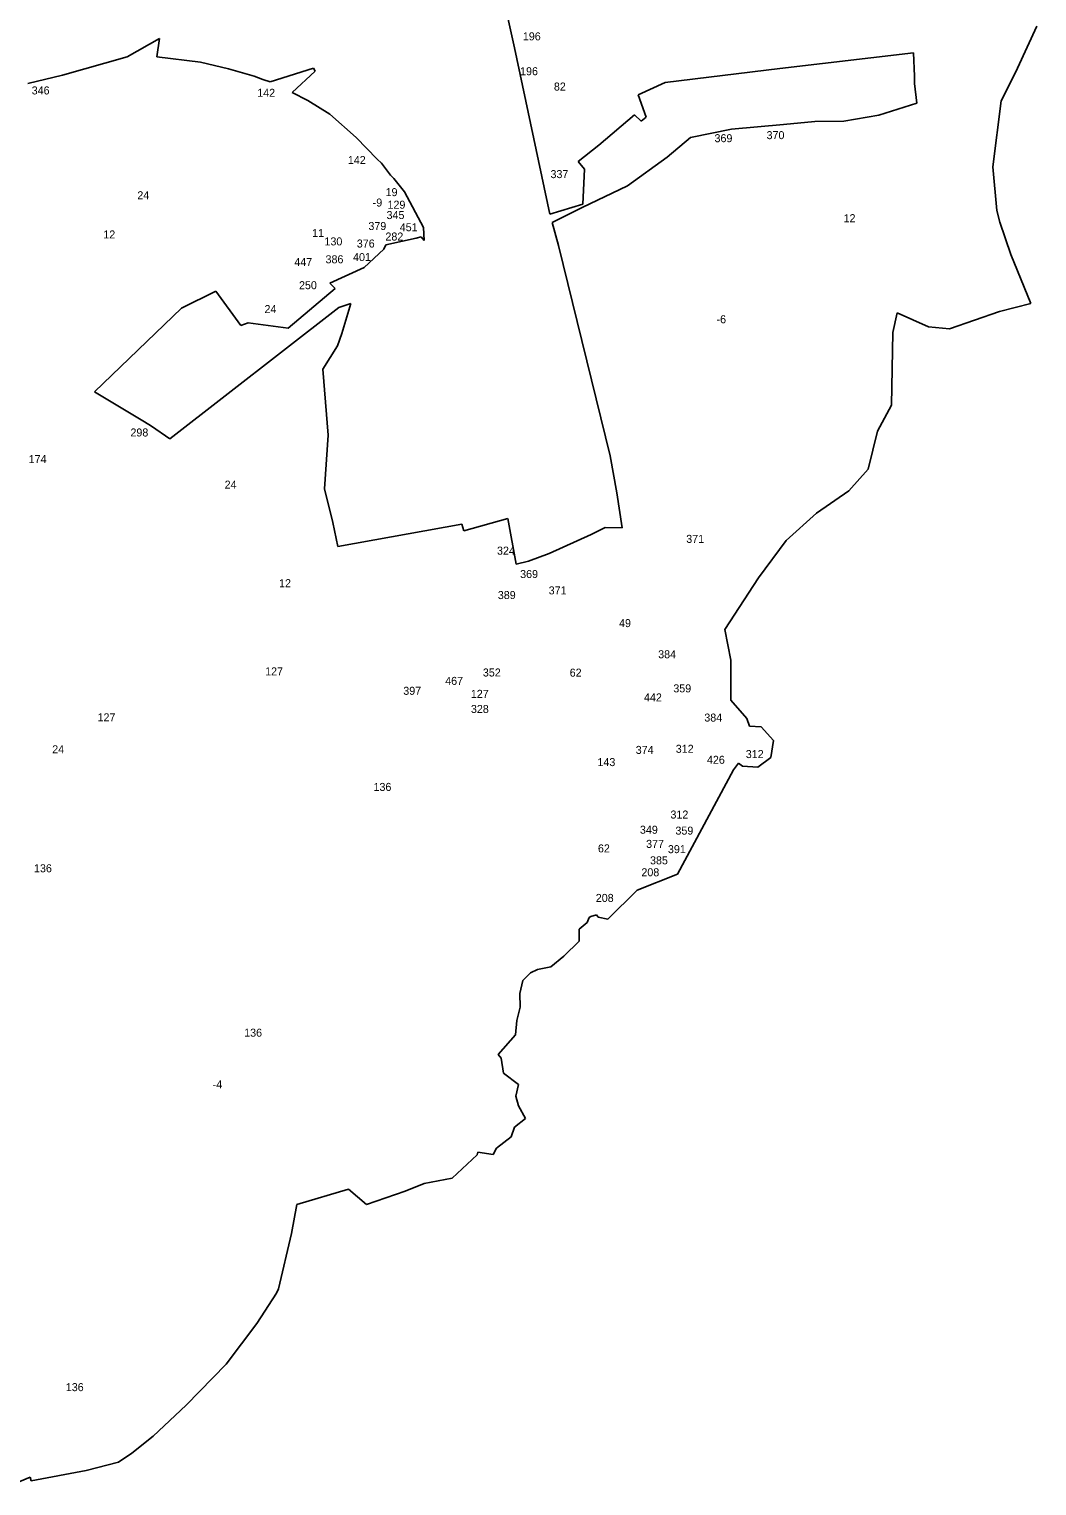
# Model space of a CAD drawing. Extents: x -782019 to -780521, y -973594 to -971888.
# Drawn here: x -781317 to -780625, y -973578 to -972577 of the extents above; entities that cross this region are included whole.
import ezdxf

# ---------------------------------------------------------------- set-up
doc = ezdxf.new("R2010")
doc.units = 0
doc.layers.add('Vrstva 13', color=7, linetype='Continuous')
doc.layers.add('Vrstva 24', color=7, linetype='Continuous')

msp = doc.modelspace()

# ---------------------------------------------------------------- linework, layer by layer
at = {"layer": 'Vrstva 13'}
for p, q in [((-780994.91, -972538.88), (-780983.51, -972589.87)), ((-780638.04, -972603.74), (-780624.8, -972574.84)), ((-781249.52, -972595.92), (-781227.36, -972583.33)), ((-781227.36, -972583.33), (-781229.28, -972595.92)), ((-781294.1, -972608.5), (-781249.52, -972595.92)), ((-781229.28, -972595.92), (-781199.28, -972599.66)), ((-780983.51, -972589.87), (-780959.31, -972704.23)), ((-780801.25, -972604.1), (-780709.62, -972593.28)), ((-780709.62, -972593.28), (-780708.89, -972609.24)), ((-781317.9, -972614.44), (-781294.1, -972608.5)), ((-781199.28, -972599.66), (-781180.09, -972604.18)), ((-781162.4, -972609.19), (-781180.09, -972604.18)), ((-781121.6, -972603.9), (-781151.33, -972613.25)), ((-781120.51, -972605.91), (-781136.37, -972620.64)), ((-781120.51, -972605.91), (-781121.6, -972603.9)), ((-780801.25, -972604.1), (-780880.2, -972613.72)), ((-780649.37, -972626.34), (-780639.72, -972607.18)), ((-780639.72, -972607.18), (-780638.04, -972603.74)), ((-781156.38, -972611.52), (-781162.4, -972609.19)), ((-781151.33, -972613.25), (-781156.38, -972611.52)), ((-780880.2, -972613.72), (-780898.53, -972622.12)), ((-780708.89, -972609.24), (-780708.8, -972614.44)), ((-780708.8, -972614.44), (-780707.34, -972627.76)), ((-781136.37, -972620.64), (-781125.57, -972626.03)), ((-781110.35, -972635.47), (-781125.57, -972626.03)), ((-780898.53, -972622.12), (-780893.15, -972637.57)), ((-780707.34, -972627.76), (-780733.24, -972636.15)), ((-780655.03, -972671.69), (-780649.37, -972626.34)), ((-781110.35, -972635.47), (-781092.33, -972651.47)), ((-780925.66, -972656.64), (-780901.18, -972635.94)), ((-780896.66, -972640.31), (-780901.18, -972635.94)), ((-780896.66, -972640.31), (-780893.15, -972637.57)), ((-780733.24, -972636.15), (-780757.26, -972640.21)), ((-780862.62, -972651.44), (-780834.62, -972645.64)), ((-780798.79, -972642.63), (-780834.62, -972645.64)), ((-780798.79, -972642.63), (-780777.19, -972640.35)), ((-780757.26, -972640.21), (-780777.19, -972640.35)), ((-781077.93, -972666.34), (-781092.33, -972651.47)), ((-780939.84, -972667.86), (-780925.66, -972656.64)), ((-780878.62, -972664.98), (-780862.62, -972651.44)), ((-781075.01, -972669.16), (-781077.93, -972666.34)), ((-781068.63, -972677.28), (-781075.01, -972669.16)), ((-780935.42, -972673.29), (-780939.84, -972667.86)), ((-780906.01, -972684.59), (-780878.62, -972664.98)), ((-781068.63, -972677.28), (-781066.53, -972679.65)), ((-780935.42, -972673.29), (-780936.55, -972697.36)), ((-780652.32, -972701.57), (-780655.03, -972671.69)), ((-781066.53, -972679.65), (-781059.15, -972688.77)), ((-781046.137, -972713.311), (-781059.15, -972688.77)), ((-780937.09, -972699.56), (-780906.01, -972684.59)), ((-780936.55, -972697.36), (-780959.31, -972704.23)), ((-780937.09, -972699.56), (-780957.7, -972709.84)), ((-780650.17, -972709.76), (-780652.32, -972701.57)), ((-781045.7, -972722.37), (-781046.137, -972713.311)), ((-780957.7, -972709.84), (-780953.32, -972725.8)), ((-780642.66, -972731.8), (-780650.17, -972709.76)), ((-781086.91, -972740.92), (-781073.33, -972728.19)), ((-781073.33, -972728.19), (-781071.92, -972725.28)), ((-781071.92, -972725.28), (-781051.13, -972720.72)), ((-781047.75, -972719.73), (-781051.13, -972720.72)), ((-781045.7, -972722.37), (-781047.75, -972719.73)), ((-780953.32, -972725.8), (-780917.77, -972870.37)), ((-780628.85, -972765.64), (-780642.66, -972731.8)), ((-781086.91, -972740.92), (-781110.3, -972751.54)), ((-781212.35, -972768.86), (-781188.65, -972757.19)), ((-781188.65, -972757.19), (-781171.47, -972780.77)), ((-781106.74, -972755.28), (-781139.1, -972782.54)), ((-781110.3, -972751.54), (-781106.74, -972755.28)), ((-781272.02, -972826.28), (-781212.35, -972768.86)), ((-781220.28, -972858.52), (-781104.27, -972768.41)), ((-781095.97, -972765.67), (-781104.27, -972768.41)), ((-781102.26, -972786.1), (-781095.97, -972765.67)), ((-780650.48, -972771.15), (-780628.85, -972765.64)), ((-781166.59, -972778.85), (-781171.47, -972780.77)), ((-781139.1, -972782.54), (-781166.59, -972778.85)), ((-780723.65, -972785.44), (-780720.78, -972771.87)), ((-780720.78, -972771.87), (-780699.31, -972781.61)), ((-780684.87, -972783.05), (-780650.48, -972771.15)), ((-781105.16, -972794.77), (-781102.26, -972786.1)), ((-780724.61, -972835.44), (-780723.65, -972785.44)), ((-780699.31, -972781.61), (-780684.87, -972783.05)), ((-781115.3, -972810.73), (-781105.16, -972794.77)), ((-781111.59, -972856.06), (-781115.3, -972810.73)), ((-781272.02, -972826.28), (-781237.71, -972847.01)), ((-780734.35, -972853.38), (-780724.61, -972835.44)), ((-781237.71, -972847.01), (-781232.87, -972849.81)), ((-781232.87, -972849.81), (-781220.28, -972858.52)), ((-781114.14, -972893), (-781111.59, -972856.06)), ((-780740.74, -972879.41), (-780734.35, -972853.38)), ((-780917.77, -972870.37), (-780913.21, -972895.63)), ((-780753.91, -972894.34), (-780740.74, -972879.41)), ((-781114.14, -972893), (-781108.39, -972916.16)), ((-780913.21, -972895.63), (-780909.61, -972919.71)), ((-780776.09, -972909.75), (-780753.91, -972894.34)), ((-781108.39, -972916.16), (-781104.84, -972932.67)), ((-781104.84, -972932.67), (-781019.78, -972917.26)), ((-781018.41, -972921.91), (-781019.78, -972917.26)), ((-780988.24, -972913.32), (-781018.41, -972921.91)), ((-780988.24, -972913.32), (-780982.5, -972944.74)), ((-780796.92, -972928.55), (-780776.09, -972909.75)), ((-780959.66, -972937.49), (-780930.94, -972924.27)), ((-780930.94, -972924.27), (-780921.19, -972919.57)), ((-780921.19, -972919.57), (-780909.61, -972919.71)), ((-780816, -972954.14), (-780796.92, -972928.55)), ((-780974.02, -972942.69), (-780959.66, -972937.49)), ((-780982.5, -972944.74), (-780974.02, -972942.69)), ((-780839.14, -972989.74), (-780816, -972954.14)), ((-780834.91, -973010.81), (-780839.14, -972989.74)), ((-780835.03, -973038.3), (-780834.91, -973010.81)), ((-780824.01, -973050.8), (-780835.03, -973038.3)), ((-780822.13, -973056.18), (-780824.01, -973050.8)), ((-780814.11, -973056.5), (-780822.13, -973056.18)), ((-780805.73, -973065.97), (-780814.11, -973056.5)), ((-780807.44, -973077.55), (-780805.73, -973065.97)), ((-780816.46, -973084.3), (-780807.44, -973077.55)), ((-780871.72, -973157.85), (-780833.1, -973086.16)), ((-780833.1, -973086.16), (-780829.78, -973081.59)), ((-780829.78, -973081.59), (-780827.07, -973083.46)), ((-780827.07, -973083.46), (-780816.46, -973084.3)), ((-780899.41, -973168.91), (-780871.72, -973157.85)), ((-780919.44, -973188.71), (-780899.41, -973168.91)), ((-780933.6, -973191.12), (-780932.21, -973187.7)), ((-780932.21, -973187.7), (-780931.17, -973186.82)), ((-780931.17, -973186.82), (-780927.26, -973185.78)), ((-780927.26, -973185.78), (-780926.07, -973187.43)), ((-780926.07, -973187.43), (-780919.44, -973188.71)), ((-780939.26, -973195.69), (-780933.6, -973191.12)), ((-780939.14, -973203.86), (-780939.26, -973195.69)), ((-780949.76, -973214.2), (-780939.14, -973203.86)), ((-780958.69, -973221.59), (-780949.76, -973214.2)), ((-780977.89, -973230.85), (-780972.5, -973225.58)), ((-780972.5, -973225.58), (-780967.75, -973223.39)), ((-780967.75, -973223.39), (-780958.69, -973221.59)), ((-780979.88, -973239.87), (-780977.89, -973230.85)), ((-780979.6, -973249.33), (-780979.88, -973239.87)), ((-780982, -973258.42), (-780979.6, -973249.33)), ((-780982.95, -973268.24), (-780982, -973258.42)), ((-780994.76, -973281.67), (-780982.95, -973268.24)), ((-780992.62, -973284.34), (-780994.76, -973281.67)), ((-780991.06, -973294.67), (-780992.62, -973284.34)), ((-780980.85, -973302.43), (-780991.06, -973294.67)), ((-780982.61, -973310.29), (-780980.85, -973302.43)), ((-780980.73, -973317.15), (-780982.61, -973310.29)), ((-780976.06, -973325.7), (-780980.73, -973317.15)), ((-780983.48, -973331.61), (-780976.06, -973325.7)), ((-780996.03, -973346.21), (-780985.94, -973338.33)), ((-780985.94, -973338.33), (-780983.48, -973331.61)), ((-781009.27, -973350.64), (-781008.8, -973348.89)), ((-781008.8, -973348.89), (-780998.26, -973350.44)), ((-780998.26, -973350.44), (-780996.03, -973346.21)), ((-781026.42, -973366.76), (-781009.27, -973350.64)), ((-781045.61, -973370.47), (-781026.42, -973366.76)), ((-781132.99, -973384.96), (-781097.64, -973374.43)), ((-781097.64, -973374.43), (-781085.27, -973384.97)), ((-781085.27, -973384.97), (-781058.66, -973375.7)), ((-781058.66, -973375.7), (-781045.61, -973370.47)), ((-781136.66, -973404.84), (-781132.99, -973384.96)), ((-781145.6, -973442.81), (-781136.66, -973404.84)), ((-781160.48, -973466.72), (-781147.15, -973445.92)), ((-781147.15, -973445.92), (-781145.6, -973442.81)), ((-781181.66, -973494.68), (-781160.48, -973466.72)), ((-781209.11, -973522.77), (-781181.66, -973494.68)), ((-781231.84, -973544.16), (-781209.11, -973522.77)), ((-781246.52, -973555.73), (-781231.84, -973544.16)), ((-781255.62, -973561.89), (-781246.52, -973555.73)), ((-781315.46, -973574.75), (-781277.72, -973567.63)), ((-781277.72, -973567.63), (-781255.62, -973561.89)), ((-781330.54, -973578.26), (-781316.13, -973572.32)), ((-781316.13, -973572.32), (-781315.46, -973574.75))]:
    msp.add_line(p, q, dxfattribs=at)

# ---------------------------------------------------------------- texts
at = {"layer": 'Vrstva 24'}
for s, p in [('196', (-780977.829, -972584.69)), ('196', (-780979.729, -972608.65)), ('346', (-781315.18, -972621.86)), ('142', (-781160.259, -972623.49)), ('82', (-780956.51, -972619.19)), ('369', (-780846.18, -972654.69)), ('370', (-780810.44, -972652.59)), ('142', (-781098.029, -972669.69)), ('337', (-780958.852, -972679.37)), ('24', (-781242.63, -972693.89)), ('19', (-781072.129, -972691.76)), ('-9', (-781080.982, -972698.92)), ('129', (-781070.789, -972700.41)), ('345', (-781071.45, -972707.52)), ('12', (-780757.53, -972709.67)), ('12', (-781265.98, -972720.86)), ('11', (-781122.568, -972719.86)), ('379', (-781083.922, -972715.06)), ('282', (-781072.23, -972722.27)), ('451', (-781062.389, -972715.9)), ('130', (-781114.098, -972725.63)), ('376', (-781091.892, -972727.09)), ('447', (-781134.791, -972739.77)), ('386', (-781113.35, -972737.92)), ('401', (-781094.447, -972736.37)), ('250', (-781131.578, -972755.73)), ('24', (-781155.28, -972772.14)), ('-6', (-780844.802, -972779.15)), ('298', (-781247.36, -972856.95)), ('174', (-781317.27, -972875.24)), ('24', (-781182.69, -972892.81)), ('371', (-780865.6, -972930.09)), ('324', (-780995.59, -972938.2)), ('369', (-780979.7, -972954.27)), ('12', (-781145.29, -972960.54)), ('389', (-780995.02, -972968.71)), ('371', (-780960.1, -972965.51)), ('49', (-780911.76, -972987.99)), ('384', (-780884.88, -973009.41)), ('127', (-781154.83, -973021.18)), ('352', (-781005.31, -973021.93)), ('62', (-780945.66, -973022.04)), ('397', (-781059.952, -973034.52)), ('467', (-781031.171, -973027.71)), ('359', (-780874.49, -973032.85)), ('127', (-781013.55, -973036.62)), ('442', (-780894.65, -973039.07)), ('127', (-781269.94, -973052.74)), ('328', (-781013.5, -973047)), ('384', (-780853.19, -973052.92)), ('24', (-781301.09, -973074.73)), ('374', (-780900.311, -973075.15)), ('312', (-780872.82, -973074.38)), ('143', (-780926.599, -973083.52)), ('426', (-780851.4, -973081.96)), ('312', (-780824.72, -973078.01)), ('136', (-781080.409, -973100.59)), ('312', (-780876.45, -973119.57)), ('349', (-780897.41, -973130.02)), ('359', (-780873.03, -973130.62)), ('62', (-780926.27, -973142.84)), ('377', (-780893.173, -973139.74)), ('391', (-780878.199, -973143.37)), ('385', (-780890.48, -973151.05)), ('136', (-781313.599, -973156.51)), ('208', (-780896.408, -973159.25)), ('208', (-780927.738, -973176.89)), ('136', (-781169.239, -973269.52)), ('-4', (-781190.872, -973305.06)), ('136', (-781291.759, -973513.16))]:
    msp.add_text(s, height=5.5, dxfattribs=at).set_placement(p)

doc.saveas('drawing.dxf')
